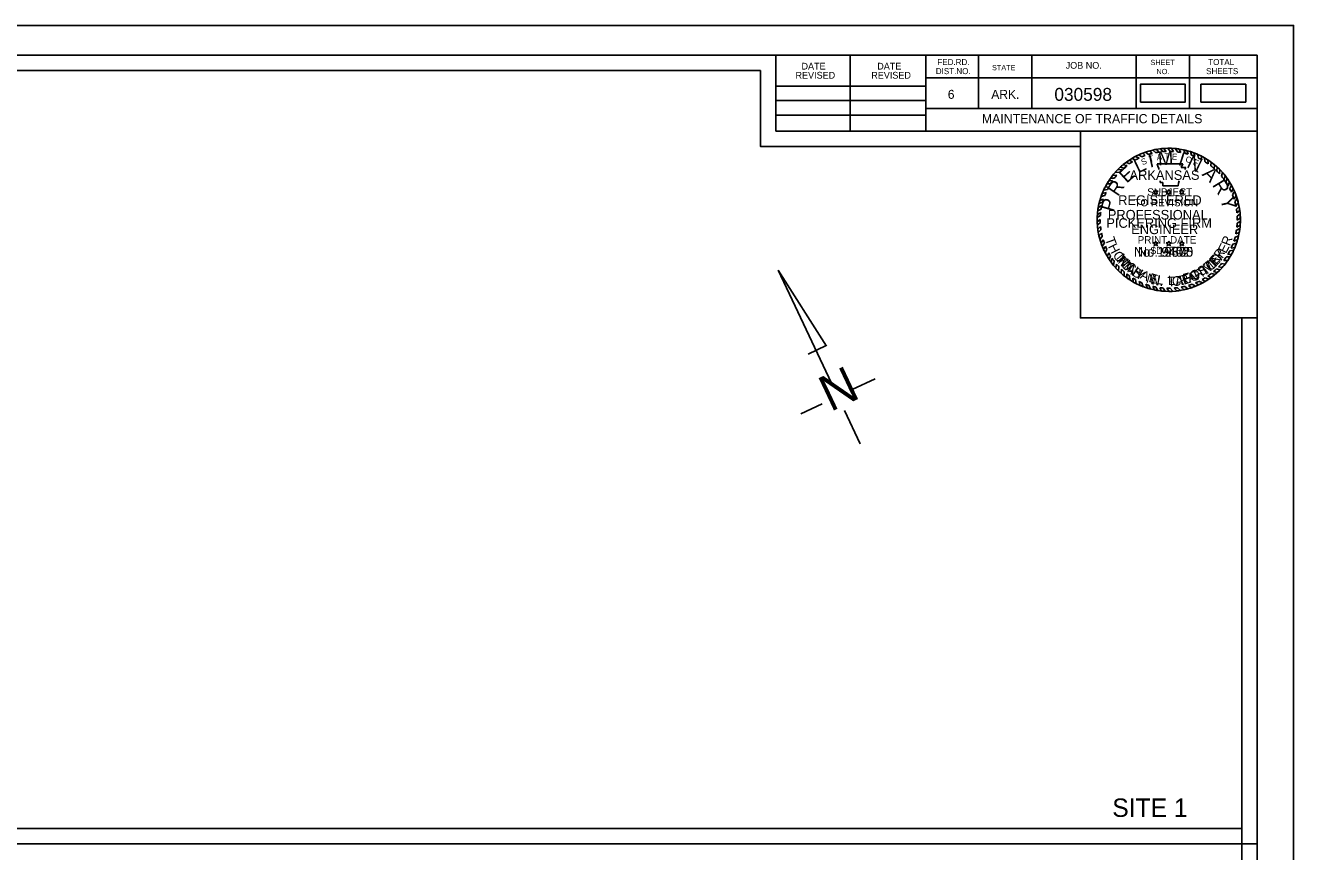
# Model space of a CAD drawing. Extents: x 1368648 to 1927880, y -1037443 to 380209.
# Drawn here: x 1374595 to 1375421, y 379215 to 379753 of the extents above; entities that cross this region are included whole.
import ezdxf

# ---------------------------------------------------------------- set-up
doc = ezdxf.new("R2010")
doc.units = 0
for name, color, linetype in [('Default', 7, 'Continuous'), ('R_Border', 7, 'Continuous'), ('R_Border Notes', 7, 'Continuous'), ('R_Border Title', 7, 'Continuous'), ('R_Draft', 7, 'Continuous'), ('R_No Plot', 7, 'Continuous'), ('STAMP_PE_CRAFTON', 7, 'Continuous'), ('STAMP_PE_FOSTER', 7, 'Continuous'), ('STAMP_PE_SEAL-INFO', 7, 'Continuous'), ('STAMP_PE_TAEGTMEYER', 7, 'Continuous'), ('STAMP_PE_TXT', 7, 'Continuous'), ('STAMP_PRELIMINARY', 7, 'Continuous')]:
    doc.layers.add(name, color=color, linetype=linetype)

msp = doc.modelspace()

# ---------------------------------------------------------------- linework, layer by layer
at = {"layer": 'Default'}
for points in [[(1375320.84, 379702.78), (1375350.01, 379702.78), (1375350.01, 379714.33), (1375320.84, 379714.33)], [(1375360.19, 379702.78), (1375389.36, 379702.78), (1375389.36, 379714.33), (1375360.19, 379714.33)]]:
    msp.add_lwpolyline(points, close=True, dxfattribs=at)
at = {"layer": 'R_Border'}
for p, q in [((1373815.87, 379733.26), (1375396.77, 379733.26)), ((1375083.57, 379683.86), (1375083.57, 379733.26)), ((1375131.97, 379683.86), (1375131.97, 379733.26)), ((1375181.27, 379733.26), (1375181.27, 379683.86)), ((1375215.47, 379733.26), (1375215.47, 379698.56)), ((1375250.17, 379733.26), (1375250.17, 379698.56)), ((1375318.07, 379733.26), (1375318.07, 379698.56)), ((1375352.77, 379733.26), (1375352.77, 379698.56)), ((1375396.77, 378705.96), (1375396.77, 379733.26)), ((1375396.77, 379718.56), (1375181.27, 379718.56)), ((1375396.77, 379718.66), (1375396.77, 379718.66)), ((1375083.57, 379713.16), (1375181.27, 379713.16)), ((1375083.57, 379703.86), (1375181.27, 379703.86)), ((1375396.77, 379698.56), (1375181.27, 379698.56)), ((1375196.07, 379698.56), (1375396.77, 379698.56)), ((1375083.57, 379694.16), (1375181.27, 379694.16)), ((1375396.77, 379683.86), (1375083.57, 379683.86)), ((1375396.77, 379219.61), (1373815.87, 379219.61))]:
    msp.add_line(p, q, dxfattribs=at)
at = {"layer": 'R_Draft'}
for p, q in [((1375085.14, 379593.32), (1375116.57, 379543.81)), ((1375119.88, 379519.76), (1375085.14, 379593.32)), ((1375104.7, 379538.69), (1375116.39, 379544.21)), ((1375133.26, 379515.47), (1375148.16, 379522.51)), ((1375099.78, 379499.66), (1375113.73, 379506.25)), ((1375138.51, 379480.29), (1375128.29, 379501.92))]:
    msp.add_line(p, q, dxfattribs=at)
at = {"layer": 'R_No Plot'}
for points in [[(1373753.84, 379752.73), (1375420.54, 379752.73), (1375420.54, 378686.04), (1373753.84, 378686.04)], [(1375386.77, 379229.61), (1373825.87, 379229.61), (1373825.87, 379723.26), (1375073.57, 379723.26), (1375073.57, 379673.86), (1375161.27, 379673.86), (1375281.77, 379673.86), (1375281.77, 379562.19), (1375386.77, 379562.19)], [(1375386.77, 379229.61), (1373825.87, 379229.61), (1373825.87, 379723.26), (1375073.57, 379723.26), (1375073.57, 379673.86), (1375161.27, 379673.86), (1375281.77, 379673.86), (1375281.77, 379562.19), (1375386.77, 379562.19)], [(1373825.87, 379723.26), (1375073.57, 379723.26), (1375073.57, 379673.86), (1375161.27, 379673.86), (1375281.77, 379673.86), (1375281.77, 379562.19), (1375386.77, 379562.19), (1375386.77, 378715.96), (1373825.87, 378715.96)], [(1375281.77, 379683.86), (1375396.77, 379683.86), (1375396.77, 379562.19), (1375281.77, 379562.19)]]:
    msp.add_lwpolyline(points, close=True, dxfattribs=at)
at = {"layer": 'STAMP_PE_SEAL-INFO'}
for p, q in [((1375315.4, 379666.1), (1375317.56, 379664.99)), ((1375317.64, 379667.36), (1375319.96, 379666.23)), ((1375319.79, 379668.42), (1375321.74, 379667.04)), ((1375322.33, 379669.49), (1375323.81, 379667.87)), ((1375324.07, 379670.13), (1375325.98, 379668.61)), ((1375327.03, 379671.04), (1375328.47, 379669.31)), ((1375328.97, 379671.53), (1375330.75, 379669.81)), ((1375331.38, 379672.01), (1375332.87, 379670.17)), ((1375333.96, 379672.38), (1375335.36, 379670.46)), ((1375337.63, 379670.61), (1375336.07, 379672.57)), ((1375340.12, 379670.63), (1375338.73, 379672.68)), ((1375342.41, 379670.53), (1375341.12, 379672.65)), ((1375344.94, 379670.27), (1375343.48, 379672.49)), ((1375347.07, 379669.95), (1375345.78, 379672.23)), ((1375349.88, 379669.36), (1375349.01, 379671.65)), ((1375351.89, 379668.81), (1375351.09, 379671.16)), ((1375354.15, 379668.08), (1375353.44, 379670.48)), ((1375356.24, 379667.28), (1375355.52, 379669.76)), ((1375358.55, 379666.25), (1375358.03, 379668.74)), ((1375360.77, 379665.11), (1375360.34, 379667.65)), ((1375362.71, 379663.97), (1375362.51, 379666.48)), ((1375306.08, 379658.8), (1375308.8, 379658.59)), ((1375307.76, 379660.41), (1375310.05, 379659.72)), ((1375309.48, 379661.92), (1375312.12, 379661.41)), ((1375311.36, 379663.55), (1375313.64, 379662.53)), ((1375313.47, 379664.88), (1375315.67, 379663.87)), ((1375331.64, 379662.52), (1375348.36, 379662.52)), ((1375332.25, 379660.99), (1375331.64, 379662.52)), ((1375332.77, 379659.5), (1375332.25, 379660.99)), ((1375332.8, 379658.93), (1375332.77, 379659.5)), ((1375348.36, 379662.52), (1375347.24, 379660.07)), ((1375347.24, 379660.07), (1375350.4, 379660.07)), ((1375350.4, 379660.07), (1375349.67, 379658.93)), ((1375364.89, 379662.54), (1375364.73, 379665.12)), ((1375366.69, 379661.21), (1375366.86, 379663.64)), ((1375368.92, 379659.35), (1375369.02, 379661.96)), ((1375370.48, 379657.88), (1375370.83, 379660.38)), ((1375372.28, 379656.02), (1375372.61, 379658.65)), ((1375298.95, 379649.45), (1375301.39, 379649.55)), ((1375300.18, 379651.45), (1375302.76, 379651.62)), ((1375301.35, 379653.17), (1375303.88, 379653.15)), ((1375302.74, 379655.02), (1375305.49, 379655.13)), ((1375304.47, 379657.08), (1375307.08, 379656.88)), ((1375333.76, 379650.38), (1375333.63, 379651.47)), ((1375335.33, 379650.38), (1375333.76, 379650.38)), ((1375335.33, 379648.23), (1375335.33, 379650.38)), ((1375345.56, 379649.92), (1375345.48, 379648.23)), ((1375345.94, 379651.47), (1375345.56, 379649.92)), ((1375373.65, 379654.44), (1375374.33, 379656.79)), ((1375375.27, 379652.35), (1375375.94, 379654.85)), ((1375376.37, 379650.77), (1375377.26, 379653.09)), ((1375377.91, 379648.29), (1375378.82, 379650.74)), ((1375295.18, 379641.19), (1375297.6, 379641.87)), ((1375295.93, 379643.22), (1375298.45, 379643.95)), ((1375296.85, 379645.38), (1375299.36, 379645.9)), ((1375297.79, 379647.33), (1375300.28, 379647.65)), ((1375345.48, 379648.23), (1375335.33, 379648.23)), ((1375378.91, 379646.45), (1375380.04, 379648.68)), ((1375380.06, 379644.03), (1375381.19, 379646.46)), ((1375380.76, 379642.35), (1375382.08, 379644.52)), ((1375381.74, 379639.6), (1375383.09, 379641.98)), ((1375295.27, 379633.11), (1375293.04, 379632)), ((1375295.7, 379635.41), (1375293.37, 379634.16)), ((1375293.87, 379636.64), (1375296.22, 379637.6)), ((1375294.4, 379638.68), (1375296.78, 379639.52)), ((1375382.28, 379637.78), (1375383.74, 379640.04)), ((1375382.94, 379634.99), (1375384.53, 379637.22)), ((1375383.29, 379633.09), (1375385.05, 379634.85)), ((1375294.79, 379628.81), (1375292.68, 379627.53)), ((1375294.71, 379626.34), (1375292.68, 379624.67)), ((1375294.74, 379624.31), (1375292.78, 379622.68)), ((1375294.97, 379630.94), (1375292.79, 379629.53)), ((1375383.62, 379630.54), (1375385.48, 379632.22)), ((1375383.78, 379628.45), (1375385.73, 379629.91)), ((1375383.79, 379623.83), (1375385.88, 379625.22)), ((1375383.84, 379625.86), (1375385.87, 379627.47)), ((1375294.91, 379621.83), (1375293.05, 379620.05)), ((1375295.17, 379619.69), (1375293.4, 379617.82)), ((1375295.56, 379617.39), (1375293.86, 379615.55)), ((1375382.88, 379616.86), (1375385.16, 379617.84)), ((1375383.33, 379619.36), (1375385.55, 379620.46)), ((1375383.59, 379621.3), (1375385.76, 379622.59)), ((1375296.03, 379615.3), (1375294.47, 379613.22)), ((1375296.65, 379613.06), (1375295.17, 379610.97)), ((1375297.35, 379610.95), (1375295.94, 379608.89)), ((1375298.18, 379608.81), (1375296.87, 379606.7)), ((1375379.86, 379607.66), (1375382.3, 379608.14)), ((1375380.93, 379610.23), (1375383.35, 379610.89)), ((1375381.61, 379612.13), (1375384.06, 379613.14)), ((1375382.34, 379614.6), (1375384.7, 379615.61)), ((1375299.04, 379606.9), (1375297.9, 379604.59)), ((1375300.21, 379604.61), (1375299.26, 379602.16)), ((1375301.39, 379602.59), (1375300.47, 379600.23)), ((1375302.41, 379601.03), (1375301.86, 379598.27)), ((1375375.14, 379599.61), (1375377.66, 379599.63)), ((1375376.84, 379602.08), (1375379.22, 379602.05)), ((1375377.7, 379603.49), (1375380.2, 379603.76)), ((1375379.06, 379605.98), (1375381.5, 379606.32)), ((1375303.81, 379599.08), (1375303.3, 379596.42)), ((1375305.33, 379597.19), (1375304.9, 379594.59)), ((1375306.84, 379595.5), (1375306.53, 379592.89)), ((1375308.45, 379593.87), (1375308.31, 379591.23)), ((1375310.18, 379592.31), (1375310.16, 379589.67)), ((1375367.03, 379591.2), (1375369.37, 379590.47)), ((1375368.38, 379592.32), (1375370.74, 379591.67)), ((1375370.41, 379594.18), (1375372.61, 379593.49)), ((1375371.68, 379595.48), (1375374.07, 379595.05)), ((1375373.6, 379597.64), (1375375.91, 379597.24)), ((1375311.98, 379590.84), (1375312.07, 379588.22)), ((1375313.67, 379589.59), (1375313.85, 379587)), ((1375315.8, 379588.18), (1375316.11, 379585.62)), ((1375317.56, 379587.15), (1375318.01, 379584.59)), ((1375319.96, 379585.9), (1375320.74, 379583.3)), ((1375321.82, 379585.06), (1375322.69, 379582.51)), ((1375324.29, 379584.1), (1375325.33, 379581.59)), ((1375326.33, 379583.42), (1375327.47, 379580.98)), ((1375352.04, 379583.37), (1375354.12, 379581.88)), ((1375354.5, 379584.18), (1375356.72, 379582.84)), ((1375356.6, 379585.01), (1375358.71, 379583.7)), ((1375358.89, 379586.05), (1375361.31, 379584.99)), ((1375360.93, 379587.12), (1375363.02, 379585.95)), ((1375363, 379588.34), (1375365.25, 379587.37)), ((1375364.72, 379589.48), (1375366.92, 379588.54)), ((1375328.87, 379582.73), (1375329.94, 379580.4)), ((1375330.86, 379582.3), (1375332.09, 379580.01)), ((1375333.36, 379581.89), (1375334.56, 379579.69)), ((1375335.55, 379581.66), (1375336.92, 379579.51)), ((1375337.97, 379581.52), (1375339.48, 379579.46)), ((1375340.27, 379581.51), (1375341.99, 379579.53)), ((1375342.86, 379581.65), (1375344.49, 379579.75)), ((1375345.05, 379581.88), (1375346.92, 379580.09)), ((1375347.28, 379582.23), (1375349.22, 379580.53)), ((1375349.74, 379582.75), (1375351.63, 379581.12))]:
    msp.add_line(p, q, dxfattribs=at)
for radius, start, end in [(46.61, 117.65441, 120.80988), (44.57, 115.68692, 119.15827), (46.61, 111.31242, 114.70259), (44.57, 110.30864, 113.16588), (46.61, 105.23389, 109.03519), (44.57, 104.03521, 107.36155), (46.61, 99.75254, 102.77648), (44.57, 98.25799, 101.03289), (46.61, 93.93815, 96.55172), (44.57, 92.11016, 95.03666), (46.61, 87.72979, 90.67067), (44.57, 85.96279, 88.9097), (46.61, 81.97315, 84.82355), (44.57, 79.92642, 82.69597), (46.61, 75.31251, 77.94263), (44.57, 73.55748, 76.23144), (46.61, 69.60611, 72.30577), (44.57, 67.62483, 70.50398), (46.61, 63.13288, 66.2704), (44.57, 61.15575, 64.37837), (46.61, 56.90029, 60.09423), (46.61, 135.40208, 138.30314), (44.57, 133.13306, 136.25623), (46.61, 129.73259, 132.53764), (44.57, 127.52969, 130.96829), (46.61, 123.61993, 126.59063), (44.57, 121.97456, 125.11001), (44.57, 54.92383, 58.27016), (44.57, 48.30163, 52.03953), (46.61, 50.3492, 53.71593), (44.57, 42.22116, 45.55119), (46.61, 44.3405, 47.39292), (46.61, 147.00719, 149.89904), (46.61, 141.60556, 144.44865), (44.57, 145.01972, 148.21036), (44.57, 139.30101, 142.58729), (44.57, 36.13503, 39.53106), (46.61, 38.12472, 41.23157), (44.57, 29.90321, 33.66454), (46.61, 31.96138, 35.42937), (46.61, 158.40766, 161.07015), (46.61, 152.86398, 155.51889), (44.57, 156.34018, 159.23194), (44.57, 151.03153, 153.57304), (44.57, 23.77322, 27.22114), (46.61, 25.93909, 29.01247), (44.57, 17.68022, 21.42509), (46.61, 19.95381, 23.31409), (46.61, 170.0003, 172.68778), (46.61, 164.3068, 166.89395), (44.57, 167.90481, 170.90393), (44.57, 162.43309, 165.00133), (44.57, 11.54445, 15.23639), (44.57, 5.7599, 9.06056), (46.61, 13.84205, 17.44468), (46.61, 7.58519, 10.86211), (46.61, 175.74093, 178.2066), (46.61, 181.72508, 184.16255), (44.57, 179.64537, 182.26333), (44.57, 173.73, 176.47337), (44.57, 359.73289, 3.06392), (46.61, 1.72155, 4.72681), (46.61, 355.71562, 358.95694), (46.61, 187.42037, 190.19271), (44.57, 185.45389, 188.23401), (44.57, 191.22736, 193.98583), (44.57, 348.07782, 351.34355), (44.57, 353.86319, 357.12742), (46.61, 349.83047, 353.08845), (46.61, 193.03695, 195.99732), (46.61, 198.89671, 201.62812), (44.57, 196.96751, 199.83526), (44.57, 202.77613, 205.47915), (44.57, 335.6038, 339.18578), (44.57, 341.77699, 345.09248), (46.61, 337.38367, 340.99332), (46.61, 343.89247, 347.03502), (46.61, 204.54793, 207.43282), (46.61, 210.86355, 213.65709), (44.57, 208.78826, 211.79343), (44.57, 214.18375, 217.27474), (44.57, 323.58513, 327.44069), (46.61, 325.44052, 328.98725), (44.57, 329.55488, 333.20757), (46.61, 331.40371, 334.93315), (46.61, 216.61154, 219.49098), (46.61, 222.47995, 225.38008), (44.57, 220.39088, 223.30564), (46.61, 228.36648, 231.34802), (44.57, 226.24938, 229.24068), (44.57, 304.82299, 308.51428), (44.57, 310.77436, 314.31605), (46.61, 312.45177, 315.66328), (44.57, 316.65308, 320.37109), (46.61, 318.28455, 321.80429), (44.57, 232.22904, 234.93361), (46.61, 234.29502, 236.94517), (44.57, 238.22227, 240.83529), (46.61, 240.1977, 242.86128), (44.57, 244.32043, 246.94859), (46.61, 246.57598, 249.15579), (44.57, 250.34912, 253.12157), (44.57, 286.64233, 289.97826), (44.57, 292.87452, 296.11851), (46.61, 294.64808, 298.21662), (44.57, 299.07679, 302.17235), (46.61, 300.62101, 303.87026), (46.61, 306.37206, 310.20799), (46.61, 252.59667, 255.32518), (44.57, 256.50505, 259.11916), (46.61, 258.44328, 261.13983), (44.57, 262.37828, 265.20115), (46.61, 264.19784, 267.10092), (44.57, 268.3215, 271.27698), (46.61, 270.25484, 273.33609), (44.57, 274.61565, 277.44863), (46.61, 276.42389, 279.43574), (44.57, 280.34588, 283.58137), (46.61, 282.31994, 285.37019), (46.61, 288.57086, 291.97334)]:
    msp.add_arc((1375339.27, 379626.07), radius, start, end, dxfattribs=at)
at = {"layer": 'STAMP_PE_TXT'}
for p, q in [((1375330.17, 379643.93), (1375329.18, 379644.65)), ((1375329.18, 379644.65), (1375330.41, 379644.65)), ((1375329.79, 379642.76), (1375330.17, 379643.93)), ((1375330.78, 379643.48), (1375329.79, 379642.76)), ((1375330.41, 379644.65), (1375330.78, 379645.81)), ((1375330.78, 379645.81), (1375331.16, 379644.65)), ((1375331.78, 379642.76), (1375330.78, 379643.48)), ((1375331.16, 379644.65), (1375332.39, 379644.65)), ((1375332.39, 379644.65), (1375331.4, 379643.93)), ((1375331.4, 379643.93), (1375331.78, 379642.76)), ((1375338.66, 379643.93), (1375337.67, 379644.65)), ((1375337.67, 379644.65), (1375338.9, 379644.65)), ((1375338.28, 379642.76), (1375338.66, 379643.93)), ((1375339.27, 379643.48), (1375338.28, 379642.76)), ((1375338.9, 379644.65), (1375339.27, 379645.81)), ((1375339.27, 379645.81), (1375339.65, 379644.65)), ((1375340.27, 379642.76), (1375339.27, 379643.48)), ((1375339.65, 379644.65), (1375340.88, 379644.65)), ((1375340.88, 379644.65), (1375339.89, 379643.93)), ((1375339.89, 379643.93), (1375340.27, 379642.76)), ((1375347.15, 379643.93), (1375346.16, 379644.65)), ((1375346.16, 379644.65), (1375347.39, 379644.65)), ((1375346.77, 379642.76), (1375347.15, 379643.93)), ((1375347.76, 379643.48), (1375346.77, 379642.76)), ((1375347.39, 379644.65), (1375347.76, 379645.81)), ((1375347.76, 379645.81), (1375348.14, 379644.65)), ((1375348.76, 379642.76), (1375347.76, 379643.48)), ((1375348.14, 379644.65), (1375349.37, 379644.65)), ((1375349.37, 379644.65), (1375348.38, 379643.93)), ((1375348.38, 379643.93), (1375348.76, 379642.76)), ((1375330.17, 379610.39), (1375329.18, 379611.11)), ((1375329.18, 379611.11), (1375330.41, 379611.11)), ((1375329.79, 379609.22), (1375330.17, 379610.39)), ((1375330.78, 379609.95), (1375329.79, 379609.22)), ((1375330.41, 379611.11), (1375330.78, 379612.28)), ((1375330.78, 379612.28), (1375331.16, 379611.11)), ((1375331.78, 379609.22), (1375330.78, 379609.95)), ((1375331.16, 379611.11), (1375332.39, 379611.11)), ((1375332.39, 379611.11), (1375331.4, 379610.39)), ((1375331.4, 379610.39), (1375331.78, 379609.22)), ((1375338.66, 379610.39), (1375337.67, 379611.11)), ((1375337.67, 379611.11), (1375338.9, 379611.11)), ((1375338.28, 379609.22), (1375338.66, 379610.39)), ((1375339.27, 379609.95), (1375338.28, 379609.22)), ((1375338.9, 379611.11), (1375339.27, 379612.28)), ((1375339.27, 379612.28), (1375339.65, 379611.11)), ((1375340.27, 379609.22), (1375339.27, 379609.95)), ((1375339.65, 379611.11), (1375340.88, 379611.11)), ((1375340.88, 379611.11), (1375339.89, 379610.39)), ((1375339.89, 379610.39), (1375340.27, 379609.22)), ((1375347.15, 379610.39), (1375346.16, 379611.11)), ((1375346.16, 379611.11), (1375347.39, 379611.11)), ((1375346.77, 379609.22), (1375347.15, 379610.39)), ((1375347.76, 379609.95), (1375346.77, 379609.22)), ((1375347.39, 379611.11), (1375347.76, 379612.28)), ((1375347.76, 379612.28), (1375348.14, 379611.11)), ((1375348.76, 379609.22), (1375347.76, 379609.95)), ((1375348.14, 379611.11), (1375349.37, 379611.11)), ((1375349.37, 379611.11), (1375348.38, 379610.39)), ((1375348.38, 379610.39), (1375348.76, 379609.22))]:
    msp.add_line(p, q, dxfattribs=at)
at = {"layer": 'STAMP_PRELIMINARY'}
msp.add_circle((1375339.27, 379626.07), 46.61, dxfattribs=at)

# ---------------------------------------------------------------- texts
at = {"layer": 'R_Border'}
for s, height, p in [('DATE', 4.396, (1375100.26, 379723.94)), ('DATE', 4.396, (1375149.56, 379723.94)), ('DIST.NO.', 3.91, (1375187.67, 379720.96)), ('FED.RD.', 3.91, (1375188.67, 379726.86)), ('STATE', 3.42, (1375224.27, 379723.46)), ('JOB NO.', 4.396, (1375272.17, 379724.46)), ('SHEET', 3.42, (1375327.37, 379726.86)), ('NO.', 3.42, (1375331.27, 379720.96)), ('SHEETS', 3.91, (1375363.57, 379720.96)), ('TOTAL', 3.91, (1375364.97, 379726.86)), ('REVISED', 4.396, (1375096.36, 379718.04)), ('REVISED', 4.396, (1375145.66, 379718.04)), ('6', 5.86, (1375195.47, 379704.86)), ('ARK.', 5.861, (1375223.77, 379704.86))]:
    msp.add_text(s, height=height, dxfattribs=at).set_placement(p)
at = {"layer": 'R_Border Notes'}
for s, height, p in [('030598', 8.4, (1375264.83, 379703.58)), ('MAINTENANCE OF TRAFFIC DETAILS', 6, (1375217.62, 379688.95))]:
    msp.add_text(s, height=height, dxfattribs=at).set_placement(p)
at = {"layer": 'R_Border Title'}
msp.add_text('SITE 1', height=12, dxfattribs=at).set_placement((1375302.5, 379237.23))
at = {"layer": 'R_Draft'}
msp.add_text('N', height=23.27, rotation=25.27231, dxfattribs=at).set_placement((1375119.05, 379500.84))
at = {"layer": 'STAMP_PE_CRAFTON'}
msp.add_text('No. 12370', height=6.25, dxfattribs=at).set_placement((1375316.58, 379602.05))
for s, rotation, p in [('T', 310.74416, (1375304.1, 379600.56)), ('O', 317.64216, (1375307.44, 379596.5)), ('O', 41.83906, (1375366.45, 379592.27)), ('N', 49.24107, (1375370.69, 379596.18)), ('N', 324.45371, (1375311.67, 379592.58)), ('Y', 331.16864, (1375316.83, 379589)), ('A', 20.51248, (1375352.68, 379584.85)), ('F', 28.78207, (1375357.58, 379586.72)), ('T', 34.11362, (1375362.16, 379589.26)), ('N', 347.47515, (1375327.11, 379584.42)), ('.', 356.89262, (1375333.25, 379583.03)), ('C', 6.01169, (1375341.63, 379582.77)), ('R', 14.81888, (1375347.11, 379583.35))]:
    msp.add_text(s, height=6.25, rotation=rotation, dxfattribs=at).set_placement(p)
at = {"layer": 'STAMP_PE_FOSTER'}
msp.add_text('No. 9402', height=6.25, dxfattribs=at).set_placement((1375319.2, 379602.05))
for s, rotation, p in [('M', 308.33902, (1375304.85, 379601.18)), ('I', 314.18423, (1375308.84, 379596.49)), ('T', 39.41938, (1375364.99, 379592.27)), ('E', 46.96131, (1375369.28, 379596.02)), ('R', 54.5031, (1375372.9, 379600.12)), ('C', 319.87327, (1375310.61, 379594.72)), ('H', 327.72349, (1375315.26, 379591.04)), ('A', 335.72761, (1375320.16, 379588.13)), ('E', 343.5779, (1375325.85, 379585.78)), ('F', 15.86908, (1375349.45, 379584.84)), ('O', 23.71897, (1375354.67, 379586.48)), ('S', 31.72336, (1375360.23, 379589.13)), ('L', 350.81148, (1375331.14, 379584.39)), ('L', 1.26658, (1375338.84, 379583.61)), ('.', 6.80354, (1375344.07, 379583.9))]:
    msp.add_text(s, height=6, rotation=rotation, dxfattribs=at).set_placement(p)
at = {"layer": 'STAMP_PE_TAEGTMEYER'}
for s, rotation, p in [('T', 289.64597, (1375297.75, 379613.62)), ('H', 296.73386, (1375299.55, 379608.7)), ('E', 63.0984, (1375376.51, 379603.73)), ('R', 69.57001, (1375379, 379608.64)), ('O', 303.77078, (1375302.51, 379603.16)), ('M', 314.20329, (1375305.78, 379598.4)), ('E', 46.80938, (1375369.47, 379594.95)), ('Y', 53.99864, (1375373.16, 379599.03)), ('A', 321.0594, (1375310.59, 379593.58)), ('S', 327.82385, (1375314.72, 379590.36)), ('E', 17.68363, (1375349.02, 379583.73)), ('G', 23.30524, (1375354.27, 379585.38)), ('T', 31.46601, (1375359.77, 379587.84)), ('M', 39.30005, (1375364.26, 379590.56)), ('N', 344.27273, (1375324.21, 379585.33)), ('.', 350.64643, (1375330.27, 379583.67)), ('T', 3.00609, (1375338.59, 379582.67)), ('A', 8.98261, (1375343.83, 379582.95))]:
    msp.add_text(s, height=6.25, rotation=rotation, dxfattribs=at).set_placement(p)
msp.add_text('No. 19605', height=6.25, dxfattribs=at).set_placement((1375316.58, 379602.05))
at = {"layer": 'STAMP_PE_TXT'}
for s, rotation, p in [('S', 23.5541, (1375322.27, 379661.59)), ('T', 16.311, (1375326.88, 379663.45)), ('A', 9.0679, (1375331.69, 379664.71)), ('T', 1.82479, (1375336.63, 379665.36)), ('E', 355.20019, (1375341.18, 379665.4)), ('O', 342.25065, (1375349.81, 379664.02)), ('F', 335.00755, (1375354.64, 379662.33))]:
    msp.add_text(s, height=3.91, rotation=rotation, dxfattribs=at).set_placement(p)
for s, p in [('ARKANSAS', (1375313.74, 379652.12)), ('REGISTERED', (1375306.36, 379635.77)), ('PROFESSIONAL', (1375299.62, 379626.27)), ('ENGINEER', (1375314.82, 379616.76))]:
    msp.add_text(s, height=6.25, dxfattribs=at).set_placement(p)
at = {"layer": 'STAMP_PRELIMINARY'}
for s, rotation, p in [('I', 12.52485, (1375326.96, 379660)), ('M', 3.10738, (1375332.45, 379661.55)), ('I', 342.31637, (1375344.79, 379661.88)), ('N', 333.9382, (1375350.33, 379660.51)), ('E', 42.35784, (1375311.9, 379649.55)), ('L', 25.51305, (1375319.32, 379656.21)), ('A', 315.65789, (1375360.5, 379655.39)), ('R', 56.22922, (1375306.13, 379640.89)), ('R', 301.38306, (1375367.34, 379648.82)), ('Y', 283.25926, (1375372.78, 379639.88)), ('P', 73.91301, (1375303.38, 379630.77))]:
    msp.add_text(s, height=9, rotation=rotation, dxfattribs=at).set_placement(p)
for s, height, p in [('SUBJECT', 4.8, (1375325.27, 379641.81)), ('TO REVISION', 4.8, (1375316.95, 379634.89)), ('PICKERING FIRM', 6.25, (1375298.64, 379620.88)), ('PRINT DATE', 4.8, (1375319.06, 379610.65)), ('$DATE$', 4.8, (1375327.44, 379603.72))]:
    msp.add_text(s, height=height, dxfattribs=at).set_placement(p)

doc.saveas('drawing.dxf')
